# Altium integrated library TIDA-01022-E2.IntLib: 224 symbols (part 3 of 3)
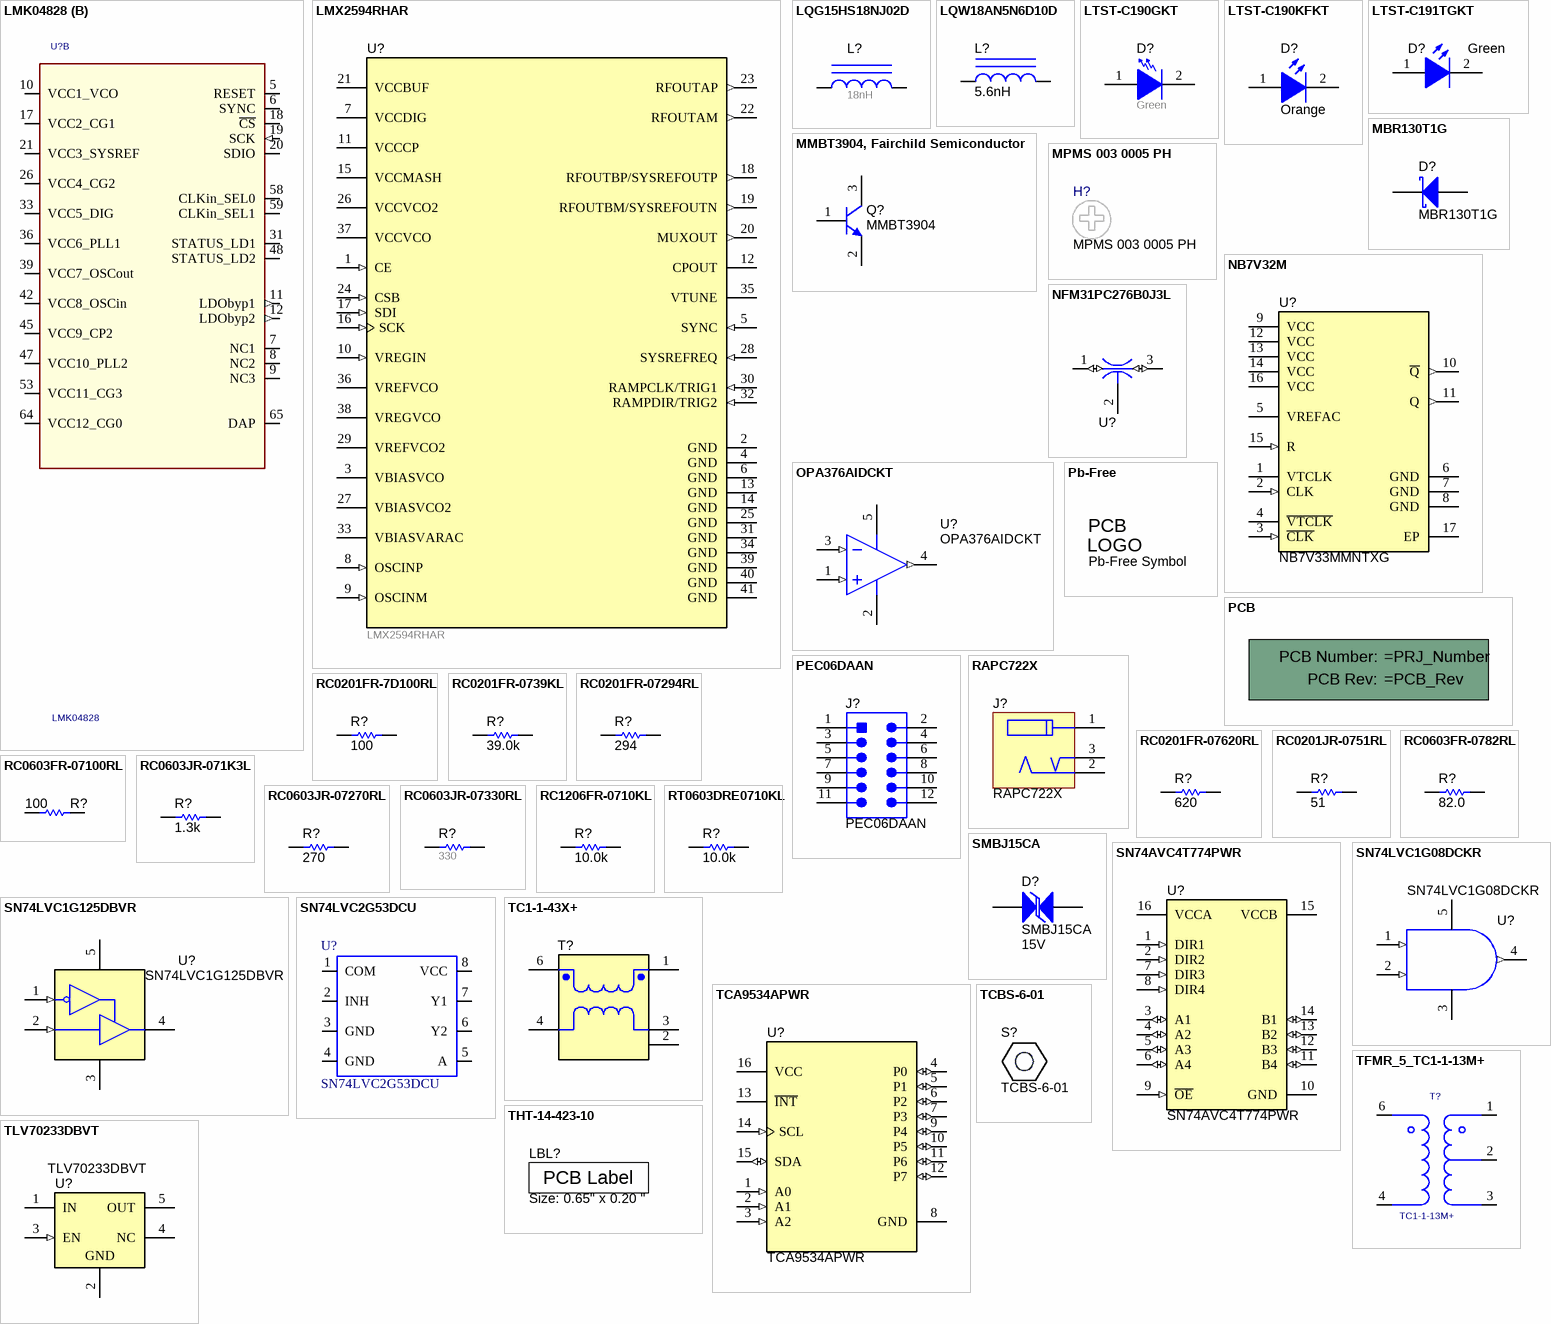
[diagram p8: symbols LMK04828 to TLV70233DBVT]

## RC0603JR-071K3L
designator R?  ValueDisplayed: 1.3k  (hidden comment: RC0603JR-071K3L)
RES, 1.3 k, 5%, 0.1 W, 0603; Manufacturer: Yageo America; CompType: Resistor; Value: 1.3k; Res_ohm: 1300; Value_Code: 1k30; Tolerance_%: 5; Power_W: 0.1; Value2: 0.1W; VDC_V: 50; TempCo: 100 ppm/C; SizeArea_mm2: 1.28; SizeX_mm: 1.6; SizeY_mm: 0.8; SizeZ_mm: 1; EIA_Code: E24; U/M: EA; AEC Category: Q200
signal-integrity model Resistor
simulation model Resistor
footprint 0603
footprint 0603M
footprint 0603L
footprint 0603_HV
footprint 0603S
pins: 1, 2

## RC0603JR-07270RL
designator R?  ValueDisplayed: 270  (hidden comment: RC0603JR-07270RL)
RES, 270, 5%, 0.1 W, 0603; Manufacturer: Yageo America; CompType: Resistor; Tolerance_%: 5; VDC_V: 50; Power_W: 0.1; Value: 270; U/M: EA; Value_Code: 270R; Value2: 0.1W; TempCo: 100 ppm/C; EIA_Code: E24; SizeArea_mm2: 1.28; SizeX_mm: 1.6; SizeY_mm: 0.8; SizeZ_mm: 1; AEC Category: Q200
signal-integrity model Resistor
simulation model Resistor
footprint 0603
footprint 0603M
footprint 0603L
footprint 0603_HV
footprint 0603S
pins: 1, 2

## RC0603JR-07330RL
designator R?  value 330  (hidden comment: RC0603JR-07330RL)
RES, 330 ohm, 5%, 0.1W, 0603; Manufacturer: Yageo America; CompType: Resistor; Tolerance_%: 5; VDC_V: 50; Power_W: 0.1; U/M: EA; Value_Code: 330R; EIA_Code: E24
signal-integrity model Resistor
simulation model Resistor
footprint 0603
footprint 0603M
footprint 0603L
footprint 0603_HV
pins: 1, 2

## RC1206FR-0710KL
designator R?  ValueDisplayed: 10.0k  (hidden comment: RC1206FR-0710KL)
RES, 10.0 k, 1%, 0.25 W, 1206; Manufacturer: Yageo America; CompType: Resistor; Value: 10.0k; Res_ohm: 10000; Value_Code: 10k0; Tolerance_%: 1; Power_W: 0.25; Value2: 0.25W; VDC_V: 200; TempCo: 100 ppm/C; SizeArea_mm2: 5.12; SizeX_mm: 3.2; SizeY_mm: 1.6; SizeZ_mm: 1.35; EIA_Code: E96; U/M: EA; AEC Category: Q200
signal-integrity model Resistor
simulation model Resistor
footprint 1206
footprint 1206M
footprint 1206L
pins: 1, 2

## RT0603DRE0710KL
designator R?  ValueDisplayed: 10.0k  (hidden comment: RT0603DRE0710KL)
RES, 10.0 k, 0.5%, 0.1 W, 0603; Manufacturer: Yageo America; CompType: Resistor; Value: 10.0k; Res_ohm: 10000; Value_Code: 10k0; Tolerance_%: 0.5; Power_W: 0.1; Value2: 0.1W; VDC_V: 75; TempCo: 50 ppm/C; SizeArea_mm2: 1.28; SizeX_mm: 1.6; SizeY_mm: 0.8; SizeZ_mm: 1; EIA_Code: E192; U/M: EA; AEC Category: Q200
signal-integrity model Resistor
simulation model Resistor
footprint 0603
footprint 0603M
footprint 0603L
footprint 0603_HV
footprint 0603S
pins: 1, 2

## SMBJ15CA
designator D?  value 15V
Diode, TVS, Bi, 15 V, 24.4 Vc, SMB; Manufacturer: Fairchild Semiconductor; U/M: EA; Vr_V: 15; Value1: W; AEC Category: Q101
footprint SMB-Bi
pins: 1, 2

## SN74AVC4T774PWR
designator U?
4-Bit Dual-Supply Bus Transceiver With Configurable Voltage-Level Shifting and 3-State Outputs, PW0016A (TSSOP-16); Manufacturer: Texas Instruments; SymbolCreator: a0411947; SizeArea_mm2: 32; SizeAreaWB_mm2: 58.8; SizeX_mm: 6.4; SizeY_mm: 5; SizeZ_mm: 1.2; CompType: IC; U/M: EA
footprint PW0016A_N
footprint PW0016A_M
footprint PW0016A_L
pins: 1 DIR1 (in), 2 DIR2 (in), 3 A1 (io), 4 A2 (io), 5 A3 (io), 6 A4 (io), 7 DIR3 (in), 8 DIR4 (in), 9 ~{OE} (in), 10 GND (power), 11 B4 (io), 12 B3 (io), 13 B2 (io), 14 B1 (io), 15 VCCB (power), 16 VCCA (power)

## SN74LVC1G08DCKR
designator U?
Single 2-Input Positive-AND Gate, DCK0005A (SOT-5); Alternate PartNumber: SN74LVC1G08DCKT; Manufacturer: Texas Instruments; CompType: IC; SizeArea_mm2: 4.2; SizeAreaWB_mm2: 9.3; SizeX_mm: 2.1; SizeY_mm: 2; SizeZ_mm: 1.1; U/M: EA
footprint DCK0005A_N
footprint DCK0005A_M
footprint DCK0005A_L
pins: 1 A (in), 2 B (in), 3 V- (power), 4 Y (out), 5 V+ (power)

## SN74LVC1G125DBVR
designator U?
Single Bus Buffer Gate With 3-State Outputs, DBV0005A (SOT-5); Alternate PartNumber: SN74LVC1G125DBVT; Manufacturer: Texas Instruments; SymbolCreator: Altium; SizeArea_mm2: 8.12; SizeAreaWB_mm2: 14.82; SizeX_mm: 2.8; SizeY_mm: 2.9; SizeZ_mm: 1.45; CompType: IC; U/M: EA
footprint DBV0005A_N (SOT23, 5-Leads, Body 2.9x1.6mm, Pitch 0.95mm, Lead Span 2.8mm, IPC Medium Density)
footprint DBV0005A_M
footprint DBV0005A_L
pins: 1 ~{OE} (in), 2 A (in), 3 GND (power), 4 Y (hiz), 5 VCC (power)

## SN74LVC2G53DCU
designator U?
IC, SPDT Analog Switch; Manufacturer: TI; Alternate Manufacturer: None; Area: 36735
footprint DCU0008A_N (TSSOP, 8-Leads, Body 2x2.3mm, Pitch 0.5mm, IPC Medium Density)
pins: 1 COM, 2 INH, 3 GND, 4 GND, 5 A, 6 Y2, 7 Y1, 8 VCC

## TC1-1-43X+
designator T?  (value not drawn)
RF Transformer, 50 ohm, SMT; Manufacturer: Minicircuits; SymbolCreator: Altium
footprint MNC_AT1521
pins: 1, 2, 3, 4, 6

## TCA9534APWR
designator U?
Remote 8-Bit I2C and Low-Power I/O Expander With Interrupt Output and Configuration Registers, PW0016A (TSSOP-16); Manufacturer: Texas Instruments; SymbolCreator: Altium; SizeArea_mm2: 32; SizeAreaWB_mm2: 58.8; SizeX_mm: 6.4; SizeY_mm: 5; SizeZ_mm: 1.2; CompType: IC; U/M: EA
footprint PW0016A_N (TSOP, 16-Leads, Body 5x4.4mm, Pitch 0.65mm, IPC Medium Density)
footprint PW0016A_M
footprint PW0016A_L
pins: 1 A0 (in), 2 A1 (in), 3 A2 (in), 4 P0 (io), 5 P1 (io), 6 P2 (io), 7 P3 (io), 8 GND (power), 9 P4 (io), 10 P5 (io), 11 P6 (io), 12 P7 (io), 13 ~{INT} (oc), 14 SCL (in), 15 SDA (io), 16 VCC (power)

## TCBS-6-01
designator S?
HEX STANDOFF SPACER, 9.53 mm; Manufacturer: Richco Plastics; SymbolCreator: a0412235
footprint TCBS-6-01

## TFMR_5_TC1-1-13M+
designator T?, comment TC1-1-13M+
RF Transformer; Manufacturer: Mini-Circuits
footprint TFMR_5_150x150_50
footprint TFMR_5_150x150_50
pins: 1 secondary_dot, 2 secondary_ct, 3 secondary, 4 primary, 6 primary_dot

## THT-14-423-10
designator LBL?, comment Size: 0.65" x 0.20 "
Thermal Transfer Printable Labels, 0.650" W x 0.200" H - 10,000 per roll; Manufacturer: Brady; PartNumber: THT-14-423-10; SymbolCreator: a0412235; CompType: Label
footprint Label_650x200

## TLV70233DBVT
designator U?
Single Output LDO, 300 mA, Fixed 3.3 V Output, 2 to 5.5 V Input, with Low IQ, 5-pin SOT-23 (DBV), -40 to 125 degC, Green (RoHS & no Sb/Br); Manufacturer: Texas Instruments; Alternate PartNumber: Equivalent; Accuracy(%): 2; Fixed Output Options(V): 3.3; Iout(Max)(A): 0.3; Iq(Typ)(mA): 0.03; SubFamily: Single Channel LDO; Vdo(Typ)(mV): 220; Vin(Max)(V): 5.5
footprint DBV0005A_N (SOT23, 5-Leads, Body 2.9x1.6mm, Pitch 0.95mm, IPC Medium Density)
footprint DBV0005A_L (SOT23, 5-Leads, Body 2.9x1.6mm, Pitch 0.95mm, IPC High Density)
footprint DBV0005A_M (SOT23, 5-Leads, Body 2.9x1.6mm, Pitch 0.95mm, IPC Low Density)
pins: 1 IN (power) "Input supply voltage", 2 GND (power) "Ground", 3 EN (in) "Enable input", 4 NC "No connected", 5 OUT (power) "Regulated output voltage"

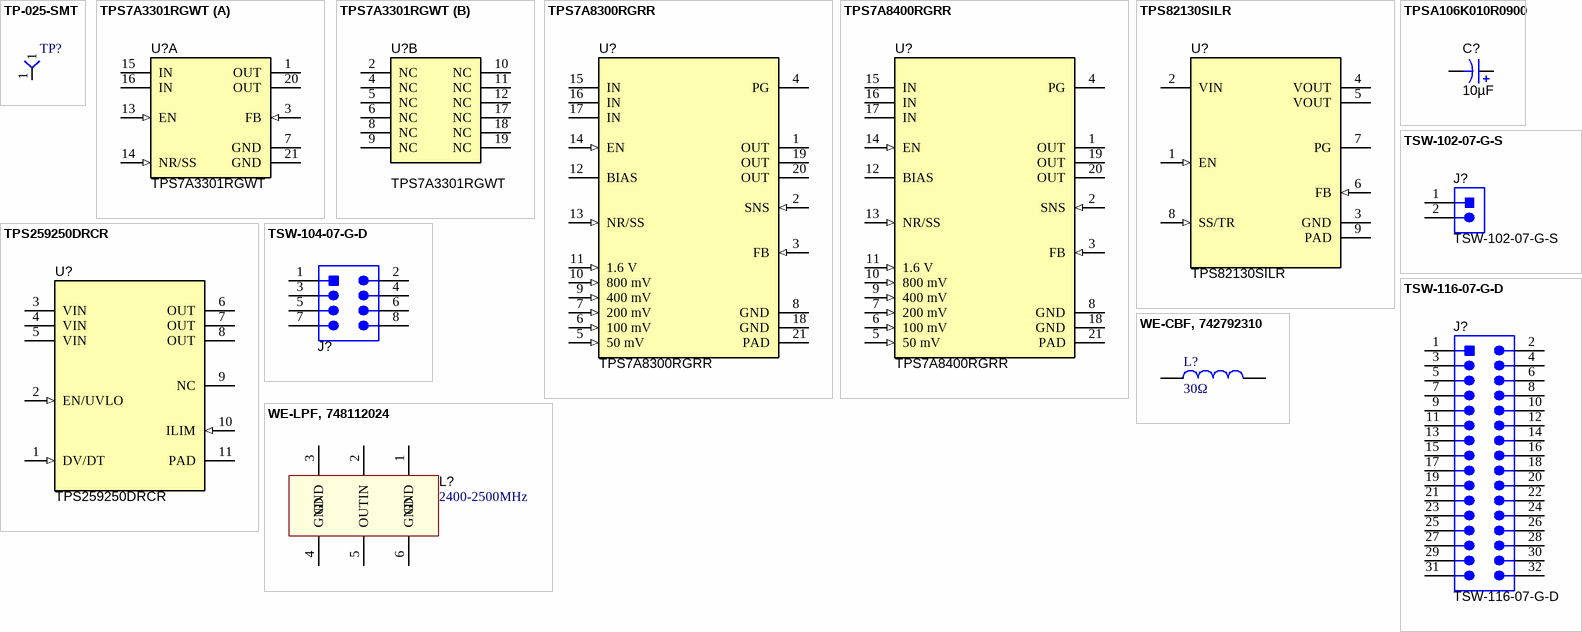
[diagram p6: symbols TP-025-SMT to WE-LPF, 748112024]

## TP-025-SMT
designator TP?  (value not drawn)
Test Point, O.025"; Manufacturer: STD; Value: STD
footprint PROBE_POINT_30PAD (Footprint not found)
pins: 1

## TPS7A3301RGWT
designator U?
Single Output High PSRR LDO, 1 A, Adjustable -1.18 to -33 V Output, -3 to -36 V Input, with Ultra-Low Noise, 20-pin VQFN (RGW), -40 to 125 degC, Green (RoHS & no Sb/Br); Manufacturer: Texas Instruments; Alternate PartNumber: Equivalent; Accuracy(%): 1.5; Iout(Max)(A): 1; Iq(Typ)(mA): 0.21; SubFamily: Single Channel LDO; Vdo(Typ)(mV): 290
footprint RGW0020A (QFN, 20-Leads, Body 5x5mm, Pitch 0.65mm, Thermal Pad 3.15x3.15mm)
part A pins: 1 OUT (power) "Regulator output. A capacitor greater than or equal to 10 uF must be tied from this pin to ground to assure stability. It is  recommended to connect a 47-uF ceramic capacitor from OUT to GND (as close to the device as (See Datasheet)", 3 FB (in) "This pin is the input to the control-loop error amplifier. It is used to set the output voltage of the device. It is recommended to connect a 0.01-uF capacitor from FB to OUT (as close to the device as possible) to maximize (See Datasheet)", 7 GND (power) "Ground", 13 EN (in) "This pin turns the regulator on or off. If VEN >=V+EN_HI or VEN=< V-EN_HI, the regulator is enabled. If V+EN_LO>= VEN>= V-EN_LO, the regulator is disabled. The EN pin can be connected to IN, if not used. |VEN| =<|VIN|.", 14 NR/SS (in) "Noise reduction pin. A capacitor connected from this pin to GND controls the soft-start function and allows RMS noise to  be reduced to very low levels. It is recommended to connect a 1-uF capacitor from NR/SS to GND (as (See Datasheet)", 15 IN (power) "Input supply. A capacitor greater than or equal to 10 nF must be tied from this pin to ground to assure stability. It is  recommended to connect a 10-uF capacitor from IN to GND (as close to the device as possible) to reduce (See Datasheet)", 16 IN (power) "Input supply. A capacitor greater than or equal to 10 nF must be tied from this pin to ground to assure stability. It is  recommended to connect a 10-uF capacitor from IN to GND (as close to the device as possible) to reduce (See Datasheet)", 20 OUT (power) "Regulator output. A capacitor greater than or equal to 10 uF must be tied from this pin to ground to assure stability. It is  recommended to connect a 47-uF ceramic capacitor from OUT to GND (as close to the device as (See Datasheet)", 21 GND (power) "TAB is internally connected to GND. An external heatsink can be installed to provide additional thermal performance."
part B pins: 2 NC "This pin can be left open or tied to any voltage between GND and IN.", 4 NC "This pin can be left open or tied to any voltage between GND and IN.", 5 NC "This pin can be left open or tied to any voltage between GND and IN.", 6 NC "This pin can be left open or tied to any voltage between GND and IN.", 8 NC "This pin can be left open or tied to any voltage between GND and IN.", 9 NC "This pin can be left open or tied to any voltage between GND and IN.", 10 NC "This pin can be left open or tied to any voltage between GND and IN.", 11 NC "This pin can be left open or tied to any voltage between GND and IN.", 12 NC "This pin can be left open or tied to any voltage between GND and IN.", 17 NC "This pin can be left open or tied to any voltage between GND and IN.", 18 NC "This pin can be left open or tied to any voltage between GND and IN.", 19 NC "This pin can be left open or tied to any voltage between GND and IN."

## TPS7A8300RGRR
designator U?
2A, Low-Dropout Voltage Regulator for High Speed Communication Systems, RGR0020A (VQFN-20); Alternate PartNumber: TPS7A8300RGRT; Manufacturer: Texas Instruments; SymbolCreator: a0411947; SizeArea_mm2: 12.25; SizeAreaWB_mm2: 20.25; SizeX_mm: 3.5; SizeZ_mm: 1; CompType: IC; U/M: EA
footprint RGR0020A
footprint RGR0020A_NV
pins: 1 OUT (power), 2 SNS (in), 3 FB (in), 4 PG (oc), 5 50 mV (in), 6 100 mV (in), 7 200 mV (in), 8 GND (power), 9 400 mV (in), 10 800 mV (in), 11 1.6 V (in), 12 BIAS (power), 13 NR/SS (in), 14 EN (in), 15 IN (power), 16 IN (power), 17 IN (power), 18 GND (power), 19 OUT (power), 20 OUT (power), 21 PAD (power)

## TPS7A8400RGRR
designator U?
High-Current (3 A), High-Accuracy (1%), Low-Noise (4.4 μVRMS), LDO Voltage Regulator, RGR0020A (VQFN-20); Alternate PartNumber: TPS7A8400RGRT; Manufacturer: Texas Instruments; SymbolCreator: a0411947; SizeArea_mm2: 12.25; SizeAreaWB_mm2: 20.25; SizeX_mm: 3.5; SizeZ_mm: 1; CompType: IC; U/M: EA
footprint RGR0020A
footprint RGR0020A_NV
pins: 1 OUT (power), 2 SNS (in), 3 FB (in), 4 PG (oc), 5 50 mV (in), 6 100 mV (in), 7 200 mV (in), 8 GND (power), 9 400 mV (in), 10 800 mV (in), 11 1.6 V (in), 12 BIAS (power), 13 NR/SS (in), 14 EN (in), 15 IN (power), 16 IN (power), 17 IN (power), 18 GND (power), 19 OUT (power), 20 OUT (power), 21 PAD (power)

## TPS82130SILR
designator U?
3-A 17V Step-down Converter Module with Integrated Inductor, SIL0008D (uSIP-8); Alternate PartNumber: TPS82130SILT; Manufacturer: Texas Instruments; SymbolCreator: Altium; SizeArea_mm2: 12.25; SizeAreaWB_mm2: 20.25; SizeX_mm: 3.5; SizeZ_mm: 1.53; CompType: IC; U/M: EA
footprint SIL0008D_SMD
pins: 1 EN (in), 2 VIN (power), 3 GND (power), 4 VOUT (power), 5 VOUT (power), 6 FB (in), 7 PG (power), 8 SS/TR (in), 9 PAD (power)

## TPS259250DRCR
designator U?
5V, 5A, 30mΩ eFuse with Adjustable +/-15% Accurate Current Limit, DRC0010J (VSON-10); Alternate PartNumber: TPS259250DRCT; Manufacturer: Texas Instruments; SymbolCreator: Altium; SizeArea_mm2: 9; SizeAreaWB_mm2: 16; SizeX_mm: 3; SizeZ_mm: 1; CompType: IC; U/M: EA
footprint DRC0010J
footprint DRC0010J_NV
pins: 1 DV/DT (in) "dV/dT", 2 EN/UVLO (in), 3 VIN (power), 4 VIN (power), 5 VIN (power), 6 OUT (power), 7 OUT (power), 8 OUT (power), 9 NC "BFET", 10 ILIM (in), 11 PAD (power)

## TPSA106K010R0900
designator C?  ValueDisplayed: 10µF  (hidden comment: TPSA106K010R0900)
CAP, TA, 10 µF, 10 V, +/- 10%, 0.9 ohm, SMD; Manufacturer: AVX; Polarized: Y; CompType: Capacitor; Value: 10uF; U/M: EA; Cap_F: 0.00001; Tolerance_%: 10; Value1: 0.9 ohm; Value2: 10V; ESR_ohm: 0.9; IRMS_A: 0.26; TaMin_C: -55; TaMax_C: 125; Cap_Case: A; SizeAreaWB_mm2: 10.92; SizeArea_mm2: 5.12; SizeX_mm: 3.2; SizeY_mm: 1.6; SizeZ_mm: 1.8; AEC Category: Q200
signal-integrity model Cap
simulation model Cap
footprint 3216-18
pins: 1 +, 2 -

## TSW-102-07-G-S
designator J?
Header, 100mil, 2x1, Gold, TH; Manufacturer: Samtec; SymbolCreator: a0412235; Pitch_mm: 2.54; Gender: Male; Shrouded: N; Row_Count: 1; Current_A: 6.3; Voltage_V: 550; Cert_CSA: Y
footprint TSW-102-07-G-S
footprint TSW-102-07-X-S
pins: 1, 2
1 alternate drawing of the same symbol

## TSW-104-07-G-D
designator J?  (value not drawn)
Header, 100mil, 4x2, Gold, TH; Manufacturer: Samtec; SymbolCreator: a0411947; Pitch_mm: 2.54; Gender: Male; Shrouded: N; Row_Count: 2; Current_A: 6.3; Voltage_V: 550; Cert_CSA: Y
footprint TSW-104-07-G-D
pins: 1, 2, 3, 4, 5, 6, 7, 8

## TSW-116-07-G-D
designator J?
Header, 100mil, 16x2, Gold, TH; Manufacturer: Samtec; SymbolCreator: a0412235; Pitch_mm: 2.54; Gender: Male; Shrouded: N; Row_Count: 2; Current_A: 6.3; Voltage_V: 550; Cert_CSA: Y; Green_Lifecycle: Active; Green_REACh: Passed
footprint TSW-116-07-G-D
pins: 1, 2, 3, 4, 5, 6, 7, 8, 9, 10, 11, 12, 13, 14, 15, 16, 17, 18, 19, 20, 21, 22, 23, 24, 25, 26, 27, 28, 29, 30, 31, 32

## WE-CBF, 742792310
designator L?, comment 30Ω
WE-CBF SMD EMI Suppression Ferrite Bead, 1210, 30Ω; PartNumber: 742792310; Type: High Current
footprint WE-CBF_1210_High Current
pins: 1, 2

## WE-LPF, 748112024
designator L?  value 2400-2500MHz  (hidden comment: WE-LPF, 748112024)
WE-LPF Multilayer Chip Low-Pass Filter, size 0603, 2400-2500MHz
footprint WE-LPF_0603
pins: 1 GND, 2 IN, 3 GND, 4 GND, 5 OUT, 6 GND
